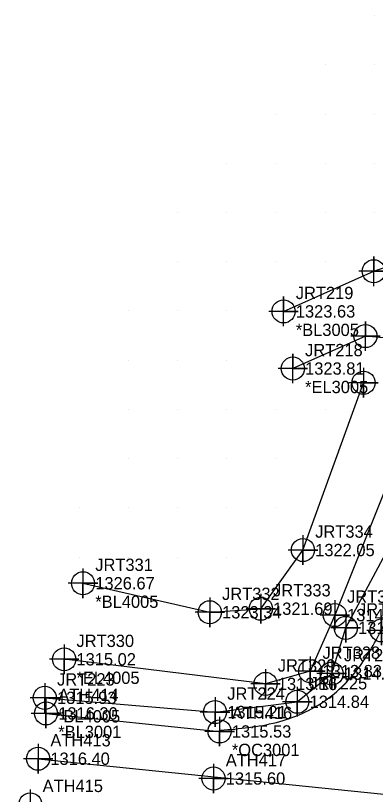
# Model space of a CAD drawing. Extents: x 1234484 to 1235382, y 695050 to 695510.
# Drawn here: x 1234507 to 1234580.2, y 695351.8 to 695510 of the extents above; entities that cross this region are included whole.
import ezdxf

# ---------------------------------------------------------------- set-up
doc = ezdxf.new("R2010")
doc.units = 0
for name, color, linetype in [('Exist DTM Breakline', 7, 'Continuous'), ('Exist DTM Breakline Cogo Comment', 7, 'Continuous'), ('Exist DTM Breakline Cogo Elevation', 7, 'Continuous'), ('Exist DTM Breakline Cogo Number', 7, 'Continuous'), ('Exist DTM Breakline Cogo Point CELL', 7, 'Continuous'), ('Exist DTM Crownline', 7, 'Continuous'), ('Exist DTM Crownline Cogo Elevation', 7, 'Continuous'), ('Exist DTM Crownline Cogo Number', 7, 'Continuous'), ('Exist DTM Crownline Cogo Point CELL', 7, 'Continuous'), ('Exist DTM QL2 LIDAR Elevation Point', 7, 'Continuous'), ('Exist Roads EOP', 7, 'Continuous'), ('Exist Roads EOP Cogo Comment', 7, 'Continuous'), ('Exist Roads EOP Cogo Elevation', 7, 'Continuous'), ('Exist Roads EOP Cogo Number', 7, 'Continuous'), ('Exist Roads EOP Cogo Point CELL', 7, 'Continuous'), ('Exist Roads Soil', 7, 'Continuous'), ('Exist Roads Soil Cogo Comment', 7, 'Continuous'), ('Exist Roads Soil Cogo Elevation', 7, 'Continuous'), ('Exist Roads Soil Cogo Number', 7, 'Continuous'), ('Exist Roads Soil Cogo Point CELL', 7, 'Continuous')]:
    doc.layers.add(name, color=color, linetype=linetype)

msp = doc.modelspace()

# ---------------------------------------------------------------- linework, layer by layer
at = {"layer": 'Exist DTM Breakline'}
for points in [[(1234512.96, 695371.423), (1234547.569, 695368.537), (1234564.304, 695370.629), (1234571.291, 695376.351), (1234574.148, 695385.63), (1234583.803, 695403.581), (1234595.326, 695434.478), (1234592.189, 695438.384)], [(1234593.455, 695436.439), (1234583.26, 695416.47), (1234571.92, 695388.234), (1234566.927, 695376.85), (1234557.842, 695374.246), (1234516.908, 695379.248)], [(1234520.732, 695394.697), (1234546.507, 695388.803), (1234556.881, 695389.527), (1234565.443, 695401.445), (1234577.768, 695435.42)]]:
    msp.add_lwpolyline(points, dxfattribs=at)
at = {"layer": 'Exist DTM Breakline Cogo Point CELL'}
for points in [[(1234577.768, 695438.42), (1234577.768, 695432.42), (1234577.768, 695435.42), (1234580.768, 695435.42), (1234574.768, 695435.42)], [(1234565.443, 695404.445), (1234565.443, 695398.445), (1234565.443, 695401.445), (1234568.443, 695401.445), (1234562.443, 695401.445)], [(1234520.732, 695397.697), (1234520.732, 695391.697), (1234520.732, 695394.697), (1234523.732, 695394.697), (1234517.732, 695394.697)], [(1234556.881, 695392.527), (1234556.881, 695386.527), (1234556.881, 695389.527), (1234559.881, 695389.527), (1234553.881, 695389.527)], [(1234546.507, 695391.803), (1234546.507, 695385.803), (1234546.507, 695388.803), (1234549.507, 695388.803), (1234543.507, 695388.803)], [(1234571.92, 695391.234), (1234571.92, 695385.234), (1234571.92, 695388.234), (1234574.92, 695388.234), (1234568.92, 695388.234)], [(1234574.148, 695388.63), (1234574.148, 695382.63), (1234574.148, 695385.63), (1234577.148, 695385.63), (1234571.148, 695385.63)], [(1234516.908, 695382.248), (1234516.908, 695376.248), (1234516.908, 695379.248), (1234519.908, 695379.248), (1234513.908, 695379.248)], [(1234566.927, 695379.85), (1234566.927, 695373.85), (1234566.927, 695376.85), (1234569.927, 695376.85), (1234563.927, 695376.85)], [(1234571.291, 695379.351), (1234571.291, 695373.351), (1234571.291, 695376.351), (1234574.291, 695376.351), (1234568.291, 695376.351)], [(1234557.842, 695377.246), (1234557.842, 695371.246), (1234557.842, 695374.246), (1234560.842, 695374.246), (1234554.842, 695374.246)], [(1234512.96, 695374.423), (1234512.96, 695368.423), (1234512.96, 695371.423), (1234515.96, 695371.423), (1234509.96, 695371.423)], [(1234564.304, 695373.629), (1234564.304, 695367.629), (1234564.304, 695370.629), (1234567.304, 695370.629), (1234561.304, 695370.629)], [(1234547.569, 695371.537), (1234547.569, 695365.537), (1234547.569, 695368.537), (1234550.569, 695368.537), (1234544.569, 695368.537)]]:
    msp.add_lwpolyline(points, dxfattribs=at)
for centre in [(1234577.768, 695435.42), (1234565.443, 695401.445), (1234520.732, 695394.697), (1234546.507, 695388.803), (1234556.881, 695389.527), (1234571.92, 695388.234), (1234574.148, 695385.63), (1234516.908, 695379.248), (1234566.927, 695376.85), (1234571.291, 695376.351), (1234557.842, 695374.246), (1234512.96, 695371.423), (1234564.304, 695370.629), (1234547.569, 695368.537)]:
    msp.add_circle(centre, 2.344, dxfattribs=at)
at = {"layer": 'Exist DTM Crownline'}
msp.add_lwpolyline([(1234511.603, 695359.057), (1234605.73, 695349.422), (1234657.657, 695344.297), (1234715.146, 695339.445), (1234769.335, 695334.825), (1234822.546, 695330.321), (1234845.176, 695328.304), (1234903.738, 695322.57)], dxfattribs=at)
at = {"layer": 'Exist DTM Crownline Cogo Point CELL'}
msp.add_lwpolyline([(1234511.603, 695362.057), (1234511.603, 695356.057), (1234511.603, 695359.057), (1234514.603, 695359.057), (1234508.603, 695359.057)], dxfattribs=at)
msp.add_circle((1234511.603, 695359.057), 2.344, dxfattribs=at)
at = {"layer": 'Exist DTM QL2 LIDAR Elevation Point'}
for p, q in [((1234580, 695510), (1234580, 695510)), ((1234570, 695500), (1234570, 695500)), ((1234580, 695500), (1234580, 695500)), ((1234560, 695490), (1234560, 695490)), ((1234570, 695490), (1234570, 695490)), ((1234580, 695490), (1234580, 695490)), ((1234550, 695480), (1234550, 695480)), ((1234560, 695480), (1234560, 695480)), ((1234570, 695480), (1234570, 695480)), ((1234580, 695480), (1234580, 695480)), ((1234540, 695470), (1234540, 695470)), ((1234550, 695470), (1234550, 695470)), ((1234560, 695470), (1234560, 695470)), ((1234570, 695470), (1234570, 695470)), ((1234580, 695470), (1234580, 695470)), ((1234540, 695460), (1234540, 695460)), ((1234550, 695460), (1234550, 695460)), ((1234560, 695460), (1234560, 695460)), ((1234570, 695460), (1234570, 695460)), ((1234530, 695450), (1234530, 695450)), ((1234540, 695450), (1234540, 695450)), ((1234550, 695450), (1234550, 695450)), ((1234530, 695440), (1234530, 695440)), ((1234540, 695440), (1234540, 695440)), ((1234550, 695440), (1234550, 695440)), ((1234530, 695430), (1234530, 695430)), ((1234540, 695430), (1234540, 695430)), ((1234550, 695430), (1234550, 695430)), ((1234560, 695430), (1234560, 695430)), ((1234570, 695430), (1234570, 695430)), ((1234530, 695420), (1234530, 695420)), ((1234540, 695420), (1234540, 695420)), ((1234550, 695420), (1234550, 695420)), ((1234560, 695420), (1234560, 695420)), ((1234520, 695410), (1234520, 695410)), ((1234530, 695410), (1234530, 695410)), ((1234540, 695410), (1234540, 695410)), ((1234550, 695410), (1234550, 695410)), ((1234560, 695410), (1234560, 695410)), ((1234520, 695400), (1234520, 695400)), ((1234530, 695400), (1234530, 695400)), ((1234540, 695400), (1234540, 695400)), ((1234550, 695400), (1234550, 695400))]:
    msp.add_line(p, q, dxfattribs=at)
at = {"layer": 'Exist Roads EOP'}
for p, q in [((1234513.204, 695368.258), (1234548.503, 695364.596)), ((1234548.503, 695364.596), (1234548.726, 695364.834))]:
    msp.add_line(p, q, dxfattribs=at)
msp.add_spline([(1234548.726, 695364.834), (1234560.064, 695366.444), (1234570.143, 695371), (1234577.785, 695378.932), (1234582.557, 695387.479)], degree=3, dxfattribs=at)
at = {"layer": 'Exist Roads EOP Cogo Point CELL'}
for points in [[(1234581.437, 695388.123), (1234581.437, 695382.123), (1234581.437, 695385.123), (1234584.437, 695385.123), (1234578.437, 695385.123)], [(1234513.204, 695371.258), (1234513.204, 695365.258), (1234513.204, 695368.258), (1234516.204, 695368.258), (1234510.204, 695368.258)], [(1234548.503, 695367.596), (1234548.503, 695361.596), (1234548.503, 695364.596), (1234551.503, 695364.596), (1234545.503, 695364.596)], [(1234547.265, 695358.039), (1234547.265, 695352.039), (1234547.265, 695355.039), (1234550.265, 695355.039), (1234544.265, 695355.039)], [(1234510.022, 695352.783), (1234510.022, 695346.783), (1234510.022, 695349.783), (1234513.022, 695349.783), (1234507.022, 695349.783)]]:
    msp.add_lwpolyline(points, dxfattribs=at)
for centre in [(1234581.437, 695385.123), (1234513.204, 695368.258), (1234548.503, 695364.596), (1234547.265, 695355.039), (1234510.022, 695349.783)]:
    msp.add_circle(centre, 2.344, dxfattribs=at)
at = {"layer": 'Exist Roads Soil'}
for points in [[(1234561.501, 695449.917), (1234579.837, 695458.059), (1234598.499, 695464.576), (1234616.621, 695466.265)], [(1234599.338, 695430.861), (1234590.269, 695443.761), (1234578.15, 695444.893), (1234563.39, 695438.311)]]:
    msp.add_lwpolyline(points, dxfattribs=at)
at = {"layer": 'Exist Roads Soil Cogo Point CELL'}
for points in [[(1234579.837, 695455.059), (1234579.837, 695461.059), (1234579.837, 695458.059), (1234582.837, 695458.059), (1234576.837, 695458.059)], [(1234561.501, 695446.917), (1234561.501, 695452.917), (1234561.501, 695449.917), (1234564.501, 695449.917), (1234558.501, 695449.917)], [(1234578.15, 695441.893), (1234578.15, 695447.893), (1234578.15, 695444.893), (1234581.15, 695444.893), (1234575.15, 695444.893)], [(1234563.39, 695435.311), (1234563.39, 695441.311), (1234563.39, 695438.311), (1234566.39, 695438.311), (1234560.39, 695438.311)]]:
    msp.add_lwpolyline(points, dxfattribs=at)
for centre in [(1234579.837, 695458.059), (1234561.501, 695449.917), (1234578.15, 695444.893), (1234563.39, 695438.311)]:
    msp.add_circle(centre, 2.344, dxfattribs=at)

# ---------------------------------------------------------------- texts
at = {"layer": 'Exist DTM Breakline Cogo Comment'}
for s, p in [('*BL4005', (1234523.232, 695389.697)), ('*EL4005', (1234519.408, 695374.248)), ('*BL4005', (1234515.46, 695366.423))]:
    msp.add_text(s, height=2.5, dxfattribs=at).set_placement(p)
at = {"layer": 'Exist DTM Breakline Cogo Elevation'}
for s, p in [('1322.05', (1234567.943, 695400.195)), ('1326.67', (1234523.232, 695393.447)), ('1321.69', (1234559.381, 695388.277)), ('1323.34', (1234549.007, 695387.553)), ('1314.40', (1234574.42, 695386.984)), ('1315.28', (1234576.648, 695384.38)), ('1315.02', (1234519.408, 695377.998)), ('1313.83', (1234569.427, 695375.6)), ('1314.95', (1234573.791, 695375.101)), ('1313.16', (1234560.342, 695372.996)), ('1315.93', (1234515.46, 695370.173)), ('1314.84', (1234566.804, 695369.379)), ('1315.21', (1234550.069, 695367.287))]:
    msp.add_text(s, height=2.5, dxfattribs=at).set_placement(p)
at = {"layer": 'Exist DTM Breakline Cogo Number'}
for s, p in [('JRT334', (1234567.943, 695403.945)), ('JRT331', (1234523.232, 695397.197)), ('JRT332', (1234549.007, 695391.303)), ('JRT333', (1234559.381, 695392.027)), ('JRT327', (1234574.42, 695390.734)), ('JRT227', (1234576.648, 695388.13)), ('JRT330', (1234519.408, 695381.748)), ('JRT328', (1234569.427, 695379.35)), ('JRT226', (1234573.791, 695378.851)), ('JRT329', (1234560.342, 695376.746)), ('JRT223', (1234515.46, 695373.923)), ('JRT225', (1234566.804, 695373.129)), ('JRT224', (1234550.069, 695371.037))]:
    msp.add_text(s, height=2.5, dxfattribs=at).set_placement(p)
at = {"layer": 'Exist DTM Crownline Cogo Elevation'}
msp.add_text('1316.40', height=2.5, dxfattribs=at).set_placement((1234514.103, 695357.807))
at = {"layer": 'Exist DTM Crownline Cogo Number'}
msp.add_text('ATH413', height=2.5, dxfattribs=at).set_placement((1234514.103, 695361.557))
at = {"layer": 'Exist Roads EOP Cogo Comment'}
for s, p in [('*BL3001', (1234515.704, 695363.258)), ('*OC3001', (1234551.003, 695359.596))]:
    msp.add_text(s, height=2.5, dxfattribs=at).set_placement(p)
at = {"layer": 'Exist Roads EOP Cogo Elevation'}
for s, p in [('1316.30', (1234515.704, 695367.008)), ('1315.53', (1234551.003, 695363.346)), ('1315.60', (1234549.765, 695353.789))]:
    msp.add_text(s, height=2.5, dxfattribs=at).set_placement(p)
at = {"layer": 'Exist Roads EOP Cogo Number'}
for s, p in [('ATH414', (1234515.704, 695370.758)), ('ATH416', (1234551.003, 695367.096)), ('ATH417', (1234549.765, 695357.539)), ('ATH415', (1234512.522, 695352.283))]:
    msp.add_text(s, height=2.5, dxfattribs=at).set_placement(p)
at = {"layer": 'Exist Roads Soil Cogo Comment'}
for s, p in [('*BL3005', (1234564.001, 695444.917)), ('*EL3005', (1234565.89, 695433.311))]:
    msp.add_text(s, height=2.5, dxfattribs=at).set_placement(p)
at = {"layer": 'Exist Roads Soil Cogo Elevation'}
for s, p in [('1323.63', (1234564.001, 695448.667)), ('1323.81', (1234565.89, 695437.061))]:
    msp.add_text(s, height=2.5, dxfattribs=at).set_placement(p)
at = {"layer": 'Exist Roads Soil Cogo Number'}
for s, p in [('JRT219', (1234564.001, 695452.417)), ('JRT218', (1234565.89, 695440.811))]:
    msp.add_text(s, height=2.5, dxfattribs=at).set_placement(p)

doc.saveas('drawing.dxf')
